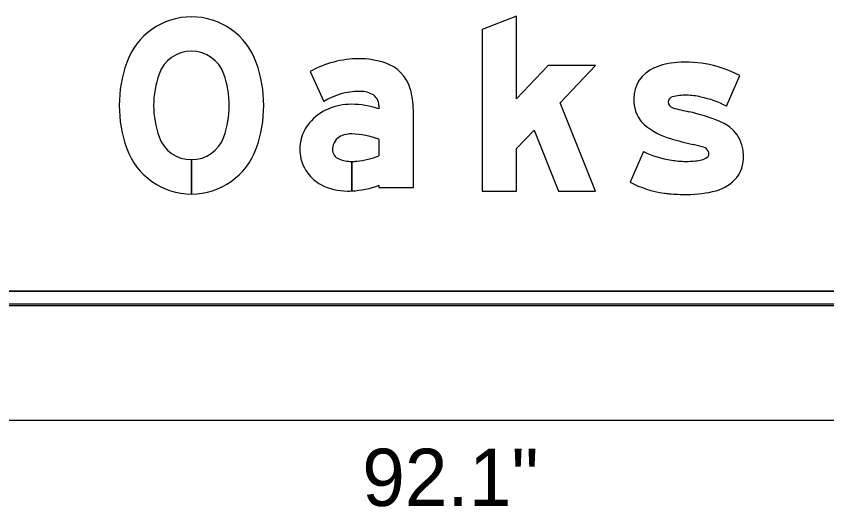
# Model space of a CAD drawing. Extents: x 1374 to 1480, y 568 to 638.
# Drawn here: x 1444.315 to 1446.672, y 598.164 to 599.591 of the extents above; entities that cross this region are included whole.
import ezdxf

# ---------------------------------------------------------------- set-up
doc = ezdxf.new("R2010")
doc.units = 0
for name, color, linetype in [('GSBWFill', 7, 'Continuous'), ('GSColorFill', 7, 'Continuous'), ('GSDims', 7, 'Continuous'), ('GSOutline', 7, 'Continuous')]:
    doc.layers.add(name, color=color, linetype=linetype)

msp = doc.modelspace()

# ---------------------------------------------------------------- linework, layer by layer
at = {"layer": 'GSBWFill'}
for p, q in [((1446.3802, 599.3294), (1446.419, 599.4185)), ((1446.1384, 599.1975), (1446.0996, 599.1084)), ((1444.8246, 599.074), (1444.8246, 599.174)), ((1444.8246, 599.174), (1444.8246, 599.074)), ((1446.0996, 599.1084), (1446.0996, 599.1084)), ((1449.9896, 598.7912), (1441.24, 598.7912)), ((1441.1146, 598.7496), (1450.1146, 598.7496)), ((1441.24, 598.7496), (1449.9896, 598.7496))]:
    msp.add_line(p, q, dxfattribs=at)
msp.add_lwpolyline([(1445.8963, 599.3392), (1445.9996, 599.4477), (1445.8615, 599.4477), (1445.7696, 599.3512), (1445.7696, 599.5915), (1445.6696, 599.5529), (1445.6696, 599.0827), (1445.7696, 599.0827), (1445.7696, 599.2062), (1445.8205, 599.2597), (1445.8918, 599.0827), (1445.9996, 599.0827)], close=True, dxfattribs=at)
for points in [[(1445.1697, 599.4302), (1445.2098, 599.3435)], [(1445.3696, 599.3313), (1445.3696, 599.3221)], [(1445.3696, 599.0997), (1445.3696, 599.0927), (1445.4696, 599.0927), (1445.4696, 599.3183)], [(1445.3696, 599.2336), (1445.3696, 599.185)], [(1445.2909, 599.083), (1445.2909, 599.1688)], [(1445.2909, 599.1688), (1445.2909, 599.083)]]:
    msp.add_lwpolyline(points, dxfattribs=at)
for centre, radius, start, end in [((1444.8246, 599.3897), 0.2, 19.6063, 160.3937), ((1444.8246, 599.3897), 0.1, 19.6063, 160.3937), ((1444.9871, 599.3318), 0.3725, 160.3938, 199.6063), ((1444.6621, 599.3318), 0.3725, 340.3938, 19.6063), ((1445.3115, 599.1811), 0.2866, 90, 119.6631), ((1445.3115, 599.223), 0.2447, 71.834, 90), ((1445.3528, 599.3486), 0.1125, 16.3165, 71.834), ((1446.2511, 599.2488), 0.2086, 94.0897, 112.8041), ((1446.2599, 599.115), 0.3428, 62.3322, 93.9601), ((1446.2082, 599.3508), 0.098, 112.8041, 180), ((1444.9871, 599.3318), 0.2725, 160.3937, 199.6063), ((1444.6621, 599.3318), 0.2725, 340.3937, 19.6062), ((1445.3115, 599.1811), 0.1916, 90, 122.0567), ((1445.3151, 599.297), 0.0758, 63.6188, 92.7072), ((1445.3321, 599.3313), 0.0375, 360, 63.6188), ((1445.2493, 599.3183), 0.2203, 0, 16.3165), ((1446.2637, 599.188), 0.1735, 90, 103.7371), ((1446.2637, 599.1972), 0.1643, 75.3298, 90), ((1445.2894, 599.1637), 0.1715, 90, 113.1768), ((1445.2894, 599.0827), 0.2524, 71.4755, 90), ((1446.2273, 599.3508), 0.117, 180, 197.7034), ((1446.2258, 599.3419), 0.015, 102.5426, 180), ((1446.2283, 599.3419), 0.0175, 180, 255.4748), ((1446.2522, 599.089), 0.2723, 61.9601, 78.7449), ((1445.2777, 599.1892), 0.1434, 112.8774, 140.1871), ((1446.1991, 599.3418), 0.0875, 197.7034, 228.9801), ((1446.3359, 599.6813), 0.3735, 252.5527, 259.9162), ((1446.1398, 598.7364), 0.5917, 68.1145, 77.234), ((1445.26, 599.2039), 0.1204, 140.1871, 180), ((1446.2695, 599.4227), 0.1947, 228.9801, 254.4047), ((1446.3221, 599.185), 0.1075, 0, 69.1882), ((1444.8246, 599.274), 0.1, 199.6063, 270), ((1444.8246, 599.274), 0.1, 270.0143, 340.3938), ((1445.2771, 599.2041), 0.0425, 113.408, 177.7075), ((1445.289, 599.1767), 0.0723, 88.6403, 113.408), ((1445.2837, 599.0032), 0.2458, 69.5454, 88.375), ((1446.5513, 600.3909), 1.2031, 253.8733, 257.1127), ((1446.1578, 598.6928), 0.5401, 73.2562, 76.5982), ((1444.8246, 599.274), 0.2, 199.6063, 270), ((1444.8246, 599.274), 0.2, 270.0072, 340.3937), ((1445.2547, 599.2039), 0.1151, 180, 216.8494), ((1445.2799, 599.2039), 0.0453, 177.7075, 180), ((1445.2646, 599.2039), 0.03, 180, 247.966), ((1446.264, 599.4664), 0.2968, 244.9593, 261.4128), ((1446.3049, 599.1859), 0.0255, 28.3809, 70.6194), ((1446.3109, 599.1904), 0.0181, 0, 24.8643), ((1445.2909, 599.2688), 0.1, 247.966, 270), ((1445.2909, 599.2688), 0.1, 270.0143, 278.1886), ((1445.2851, 599.4001), 0.2311, 274.983, 291.4646), ((1446.262, 599.3964), 0.2274, 259.2982, 270), ((1446.262, 599.4545), 0.2855, 270, 275.5479), ((1446.2877, 599.238), 0.0677, 271.594, 302.6799), ((1446.3175, 599.1904), 0.0116, 305.9611, 0), ((1446.3041, 599.185), 0.1255, 343.6227, 0), ((1446.3526, 599.1708), 0.075, 319.7324, 343.6227), ((1445.2649, 599.2116), 0.1279, 216.8494, 239.6064), ((1446.3178, 599.1986), 0.1195, 285.6227, 320.3524), ((1445.278, 599.2548), 0.1721, 243.1197, 270), ((1445.278, 599.3379), 0.2552, 272.8914, 291.0305), ((1446.2422, 599.3823), 0.3088, 242.4962, 261.8695), ((1445.278, 599.3379), 0.2552, 270, 272.8858), ((1446.2339, 599.3241), 0.25, 261.8695, 265.152), ((1446.2652, 599.6868), 0.6141, 265.1076, 270), ((1446.2652, 599.4127), 0.3399, 270, 284.4435)]:
    msp.add_arc(centre, radius, start, end, dxfattribs=at)
at = {"layer": 'GSColorFill'}
for p, q in [((1446.3802, 599.3294), (1446.419, 599.4185)), ((1446.1384, 599.1975), (1446.0996, 599.1084)), ((1444.8246, 599.074), (1444.8246, 599.174)), ((1444.8246, 599.174), (1444.8246, 599.074)), ((1446.0996, 599.1084), (1446.0996, 599.1084)), ((1449.9896, 598.7912), (1441.24, 598.7912)), ((1450.1105, 598.7537), (1441.1146, 598.7537)), ((1441.1146, 598.7496), (1450.1146, 598.7496)), ((1441.1146, 598.7496), (1450.1146, 598.7496)), ((1441.24, 598.7496), (1449.9896, 598.7496))]:
    msp.add_line(p, q, dxfattribs=at)
msp.add_lwpolyline([(1445.8963, 599.3392), (1445.9996, 599.4477), (1445.8615, 599.4477), (1445.7696, 599.3512), (1445.7696, 599.5915), (1445.6696, 599.5529), (1445.6696, 599.0827), (1445.7696, 599.0827), (1445.7696, 599.2062), (1445.8205, 599.2597), (1445.8918, 599.0827), (1445.9996, 599.0827)], close=True, dxfattribs=at)
for points in [[(1445.1697, 599.4302), (1445.2098, 599.3435)], [(1445.3696, 599.3313), (1445.3696, 599.3221)], [(1445.3696, 599.0997), (1445.3696, 599.0927), (1445.4696, 599.0927), (1445.4696, 599.3183)], [(1445.3696, 599.2336), (1445.3696, 599.185)], [(1445.2909, 599.083), (1445.2909, 599.1688)], [(1445.2909, 599.1688), (1445.2909, 599.083)]]:
    msp.add_lwpolyline(points, dxfattribs=at)
for centre, radius, start, end in [((1444.8246, 599.3897), 0.2, 19.6063, 160.3937), ((1444.8246, 599.3897), 0.1, 19.6063, 160.3937), ((1444.9871, 599.3318), 0.3725, 160.3938, 199.6063), ((1444.6621, 599.3318), 0.3725, 340.3938, 19.6063), ((1445.3115, 599.1811), 0.2866, 90, 119.6631), ((1445.3115, 599.223), 0.2447, 71.834, 90), ((1445.3528, 599.3486), 0.1125, 16.3165, 71.834), ((1446.2511, 599.2488), 0.2086, 94.0897, 112.8041), ((1446.2599, 599.115), 0.3428, 62.3322, 93.9601), ((1446.2082, 599.3508), 0.098, 112.8041, 180), ((1444.9871, 599.3318), 0.2725, 160.3937, 199.6063), ((1444.6621, 599.3318), 0.2725, 340.3937, 19.6062), ((1445.3115, 599.1811), 0.1916, 90, 122.0567), ((1445.3151, 599.297), 0.0758, 63.6188, 92.7072), ((1445.3321, 599.3313), 0.0375, 360, 63.6188), ((1445.2493, 599.3183), 0.2203, 0, 16.3165), ((1446.2637, 599.188), 0.1735, 90, 103.7371), ((1446.2637, 599.1972), 0.1643, 75.3298, 90), ((1445.2894, 599.1637), 0.1715, 90, 113.1768), ((1445.2894, 599.0827), 0.2524, 71.4755, 90), ((1446.2273, 599.3508), 0.117, 180, 197.7034), ((1446.2258, 599.3419), 0.015, 102.5426, 180), ((1446.2283, 599.3419), 0.0175, 180, 255.4748), ((1446.2522, 599.089), 0.2723, 61.9601, 78.7449), ((1445.2777, 599.1892), 0.1434, 112.8774, 140.1871), ((1446.1991, 599.3418), 0.0875, 197.7034, 228.9801), ((1446.3359, 599.6813), 0.3735, 252.5527, 259.9162), ((1446.1398, 598.7364), 0.5917, 68.1145, 77.234), ((1445.26, 599.2039), 0.1204, 140.1871, 180), ((1446.2695, 599.4227), 0.1947, 228.9801, 254.4047), ((1446.3221, 599.185), 0.1075, 0, 69.1882), ((1444.8246, 599.274), 0.1, 199.6063, 270), ((1444.8246, 599.274), 0.1, 270.0143, 340.3938), ((1445.2771, 599.2041), 0.0425, 113.408, 177.7075), ((1445.289, 599.1767), 0.0723, 88.6403, 113.408), ((1445.2837, 599.0032), 0.2458, 69.5454, 88.375), ((1446.5513, 600.3909), 1.2031, 253.8733, 257.1127), ((1446.1578, 598.6928), 0.5401, 73.2562, 76.5982), ((1444.8246, 599.274), 0.2, 199.6063, 270), ((1444.8246, 599.274), 0.2, 270.0072, 340.3937), ((1445.2547, 599.2039), 0.1151, 180, 216.8494), ((1445.2799, 599.2039), 0.0453, 177.7075, 180), ((1445.2646, 599.2039), 0.03, 180, 247.966), ((1446.264, 599.4664), 0.2968, 244.9593, 261.4128), ((1446.3049, 599.1859), 0.0255, 28.3809, 70.6194), ((1446.3109, 599.1904), 0.0181, 0, 24.8643), ((1445.2909, 599.2688), 0.1, 247.966, 270), ((1445.2909, 599.2688), 0.1, 270.0143, 278.1886), ((1445.2851, 599.4001), 0.2311, 274.983, 291.4646), ((1446.262, 599.3964), 0.2274, 259.2982, 270), ((1446.262, 599.4545), 0.2855, 270, 275.5479), ((1446.2877, 599.238), 0.0677, 271.594, 302.6799), ((1446.3175, 599.1904), 0.0116, 305.9611, 0), ((1446.3041, 599.185), 0.1255, 343.6227, 0), ((1446.3526, 599.1708), 0.075, 319.7324, 343.6227), ((1445.2649, 599.2116), 0.1279, 216.8494, 239.6064), ((1446.3178, 599.1986), 0.1195, 285.6227, 320.3524), ((1445.278, 599.2548), 0.1721, 243.1197, 270), ((1445.278, 599.3379), 0.2552, 272.8914, 291.0305), ((1446.2422, 599.3823), 0.3088, 242.4962, 261.8695), ((1445.278, 599.3379), 0.2552, 270, 272.8858), ((1446.2339, 599.3241), 0.25, 261.8695, 265.152), ((1446.2652, 599.6868), 0.6141, 265.1076, 270), ((1446.2652, 599.4127), 0.3399, 270, 284.4435)]:
    msp.add_arc(centre, radius, start, end, dxfattribs=at)
at = {"layer": 'GSDims'}
msp.add_line((1441.7771, 598.4162), (1449.4521, 598.4162), dxfattribs=at)
at = {"layer": 'GSOutline'}
for p, q in [((1446.3802, 599.3294), (1446.419, 599.4185)), ((1446.1384, 599.1975), (1446.0996, 599.1084)), ((1446.0996, 599.1084), (1446.0996, 599.1084)), ((1441.2396, 598.7912), (1449.9896, 598.7912)), ((1441.1146, 598.7496), (1450.1146, 598.7496)), ((1441.2396, 598.7496), (1449.9896, 598.7496))]:
    msp.add_line(p, q, dxfattribs=at)
msp.add_lwpolyline([(1445.8963, 599.3392), (1445.9996, 599.4477), (1445.8615, 599.4477), (1445.7696, 599.3512), (1445.7696, 599.5915), (1445.6696, 599.5529), (1445.6696, 599.0827), (1445.7696, 599.0827), (1445.7696, 599.2062), (1445.8205, 599.2597), (1445.8918, 599.0827), (1445.9996, 599.0827)], close=True, dxfattribs=at)
for points in [[(1445.1697, 599.4302), (1445.2098, 599.3435)], [(1445.3696, 599.3313), (1445.3696, 599.3221)], [(1445.3696, 599.0997), (1445.3696, 599.0927), (1445.4696, 599.0927), (1445.4696, 599.3183)], [(1445.3696, 599.2336), (1445.3696, 599.185)], [(1445.2909, 599.083), (1445.2909, 599.1688)], [(1445.2909, 599.1688), (1445.2909, 599.083)]]:
    msp.add_lwpolyline(points, dxfattribs=at)
for centre, radius, start, end in [((1444.8246, 599.3897), 0.2, 19.6063, 160.3937), ((1444.8246, 599.3897), 0.1, 19.6063, 160.3937), ((1444.9871, 599.3318), 0.3725, 160.3937, 199.6063), ((1444.6621, 599.3318), 0.3725, 340.3937, 19.6062), ((1445.3115, 599.1811), 0.2866, 90, 119.6631), ((1445.3115, 599.223), 0.2447, 71.834, 90), ((1445.3528, 599.3486), 0.1125, 16.3165, 71.834), ((1446.2511, 599.2488), 0.2086, 94.0897, 112.8041), ((1446.2599, 599.115), 0.3428, 62.3322, 93.9601), ((1446.2082, 599.3508), 0.098, 112.8041, 180), ((1444.9871, 599.3318), 0.2725, 160.3937, 199.6063), ((1444.6621, 599.3318), 0.2725, 340.3937, 19.6062), ((1445.3115, 599.1811), 0.1916, 90, 122.0567), ((1445.3151, 599.297), 0.0758, 63.6188, 92.7072), ((1445.3321, 599.3313), 0.0375, 360, 63.6188), ((1445.2493, 599.3183), 0.2203, 0, 16.3165), ((1446.2637, 599.188), 0.1735, 90, 103.7371), ((1446.2637, 599.1972), 0.1643, 75.3298, 90), ((1445.2894, 599.1637), 0.1715, 90, 113.1768), ((1445.2894, 599.0827), 0.2524, 71.4755, 90), ((1446.2273, 599.3508), 0.117, 180, 197.7034), ((1446.2258, 599.3419), 0.015, 102.5426, 180), ((1446.2283, 599.3419), 0.0175, 180, 255.4748), ((1446.2522, 599.089), 0.2723, 61.9601, 78.7449), ((1445.2777, 599.1892), 0.1434, 112.8774, 140.1871), ((1446.1991, 599.3418), 0.0875, 197.7034, 228.9801), ((1446.3359, 599.6813), 0.3735, 252.5527, 259.9162), ((1446.1398, 598.7364), 0.5917, 68.1145, 77.234), ((1445.26, 599.2039), 0.1204, 140.1871, 180), ((1446.2695, 599.4227), 0.1947, 228.9801, 254.4047), ((1446.3221, 599.185), 0.1075, 0, 69.1882), ((1444.8246, 599.274), 0.1, 199.6063, 340.3938), ((1445.2771, 599.2041), 0.0425, 113.408, 177.7075), ((1445.289, 599.1767), 0.0723, 88.6403, 113.408), ((1445.2837, 599.0032), 0.2458, 69.5454, 88.375), ((1446.5513, 600.3909), 1.2031, 253.8733, 257.1127), ((1446.1578, 598.6928), 0.5401, 73.2562, 76.5982), ((1444.8246, 599.274), 0.2, 199.6063, 340.3938), ((1445.2547, 599.2039), 0.1151, 180, 216.8494), ((1445.2799, 599.2039), 0.0453, 177.7075, 180), ((1445.2646, 599.2039), 0.03, 180, 247.966), ((1446.264, 599.4664), 0.2968, 244.9593, 261.4128), ((1446.3049, 599.1859), 0.0255, 28.3809, 70.6194), ((1446.3109, 599.1904), 0.0181, 0, 24.8643), ((1445.2909, 599.2688), 0.1, 247.966, 270), ((1445.2909, 599.2688), 0.1, 270.0143, 278.1886), ((1445.2851, 599.4001), 0.2311, 274.983, 291.4646), ((1446.262, 599.3964), 0.2274, 259.2982, 270), ((1446.262, 599.4545), 0.2855, 270, 275.5479), ((1446.2877, 599.238), 0.0677, 271.594, 302.6799), ((1446.3175, 599.1904), 0.0116, 305.9611, 0), ((1446.3041, 599.185), 0.1255, 343.6227, 0), ((1446.3526, 599.1708), 0.075, 319.7324, 343.6227), ((1445.2649, 599.2116), 0.1279, 216.8494, 239.6064), ((1446.3178, 599.1986), 0.1195, 285.6227, 320.3524), ((1445.278, 599.2548), 0.1721, 243.1197, 270), ((1445.278, 599.3379), 0.2552, 272.8914, 291.0305), ((1446.2422, 599.3823), 0.3088, 242.4962, 261.8695), ((1445.278, 599.3379), 0.2552, 270, 272.8858), ((1446.2339, 599.3241), 0.25, 261.8695, 265.152), ((1446.2652, 599.6868), 0.6141, 265.1076, 270), ((1446.2652, 599.4127), 0.3399, 270, 284.4435)]:
    msp.add_arc(centre, radius, start, end, dxfattribs=at)

# ---------------------------------------------------------------- texts
at = {"layer": 'GSDims'}
msp.add_text('92.1"', height=0.16667, dxfattribs=at).set_placement((1445.321, 598.1662))

doc.saveas('drawing.dxf')
